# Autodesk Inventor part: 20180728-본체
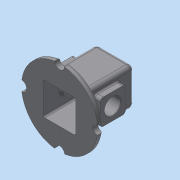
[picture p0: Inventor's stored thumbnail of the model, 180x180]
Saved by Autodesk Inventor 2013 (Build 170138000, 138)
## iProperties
Created: 2018-07
Part Number: 20180728-본체
Material: 일반
Document SubType Name: Modeling
Designer: dgall
Density: 1 g/cm^3
Author: dgall
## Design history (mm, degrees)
sketch "스케치1"
  geometry: A1 r 10 centre (0, -75) between (9.978, -74.333) and (-9.978, -74.333); A2 r 10 centre (-75, 0) between (-74.333, -9.978) and (-74.333, 9.978); A3 r 10 centre (0, 75) between (-9.978, 74.333) and (9.978, 74.333); A4 r 10 centre (75, 0) between (74.333, 9.978) and (74.333, -9.978); A5 r 75 centre (0, 0) between (-74.333, -9.978) and (-9.978, -74.333); A6 r 75 centre (0, 0) between (-9.978, 74.333) and (-74.333, 9.978); A7 r 75 centre (0, 0) between (9.978, -74.333) and (74.333, -9.978); A8 r 75 centre (0, 0) between (74.333, 9.978) and (9.978, 74.333); 1 further point
  constraints: 16 point on circle, 8 centre point, 6 equal radius, 2 horizontal alignment, 2 vertical alignment, 1 coincident
  dimensions: "d2" = 20 diameter of A1; "d3" = 75 radius of A7; "d4" = 75 distance of point (0, 0) A1.centre; "d5" = 150 distance of A2.centre A4.centre; "d6" = 75 distance of point (0, 0) A4.centre; "d7" = 75 distance of A3.centre point (0, 0)
extrude "돌출1" new body sketch "스케치1" distance "d8" = 10; taper "d9" = 0 deg
sketch "스케치2"
  geometry: L1 (-9.978, 0)-(-74.333, 0) reference; L2 (-9.978, 0)-(-9.978, -10) reference; L3 (-74.333, -10)-(-9.978, -10) reference; L4 (-74.333, 0)-(-74.333, -10) reference; L5 (9.978, 0)-(-9.978, 0) reference; L6 (9.978, 0)-(9.978, -10) reference; L7 (-9.978, -10)-(9.978, -10) reference; L8 (-9.978, 0)-(-9.978, -10) reference; L9 (74.333, 0)-(9.978, 0) reference; L10 (74.333, 0)-(74.333, -10) reference; L11 (9.978, -10)-(74.333, -10) reference; L12 (9.978, 0)-(9.978, -10) reference; L13 (-37, 0)-(-37, 100); L14 (-37, 100)-(37, 100); L15 (37, 100)-(37, 0); L16 (32, -10)-(32, 95); L17 (32, 95)-(-32, 95); L18 (-32, 95)-(-32, -10); L19 (-32, -10)-(32, -10); L20 (-37, 0)-(37, 0); 4 further points
  constraints: 16 end point, 4 midpoint, 4 perpendicular, 2 parallel, 2 point on line, 1 collinear, 1 vertical alignment
  dimensions: "d10" = 74 distance of L13.end L14.end; "d12" = 110 distance between parallel lines of L11 L14; "d13" = 5 distance between parallel lines of L14 L17; "d14" = 5 distance between parallel lines of L15 L16; "d15" = 5 distance between parallel lines of L13 L18
  node "투영된 루프1"
  node "투영된 루프2"
  node "투영된 루프3"
extrude "돌출2" join sketch "스케치2" stored distance "d16" = 74; taper "d17" = 0 deg
extrude "돌출3" cut sketch "스케치2" stored distance "d18" = 64; taper "d19" = 0 deg
sketch "스케치3"
  geometry: L1 (17, 57)-(57, 57); L2 (57, 57)-(57, 17); L3 (57, 17)-(17, 17); L4 (17, 17)-(17, 57); L5 (19.5, 54.5)-(54.5, 54.5); L6 (54.5, 54.5)-(54.5, 19.5); L7 (54.5, 19.5)-(19.5, 19.5); L8 (19.5, 19.5)-(19.5, 54.5); 5 further points
  constraints: 16 end point, 4 midpoint, 4 parallel, 4 perpendicular, 2 horizontal, 2 horizontal alignment, 2 vertical alignment
  dimensions: "d20" = 40 distance of L1.start L1.end; "d22" = 35 distance of L5.start L5.end
extrude "돌출4" join sketch "스케치3" distance "d23" = 7; taper "d24" = 0 deg
extrude "돌출5" join sketch "스케치3" distance "d25" = 10; taper "d26" = 0 deg
hole "구멍1" diameter "d29" = 21; stored, may be unused: countersink angle "d33" = 90 deg, drill point angle "d35" = 118 deg; dims "d27" = 17.5, "d28" = 17.5, "d30" = 6, "d31" = 28, "d32" = 4, "d34" = 8
sketch "스케치5"
  geometry: L1 (-74, 100)-(0, 100) reference; L2 (-62, 70)-(-12, 70); L3 (-12, 70)-(-12, 20); L4 (-12, 20)-(-62, 20); L5 (-62, 20)-(-62, 70); L6 (-62, 45)-(-12, 45); L7 (-27.022, -10)-(37.333, -10) reference; 3 further points
  constraints: 10 end point, 4 midpoint, 2 parallel, 2 perpendicular, 1 horizontal, 1 vertical alignment
  dimensions: "d37" = 50 distance of L2.start L2.end; "d39" = 55 distance between parallel lines of L7 L6
extrude "돌출6" join sketch "스케치5" distance "d40" = 13; taper "d41" = 0 deg
sketch "스케치6"
  geometry: L1 (0, 105)-(-64, 105) reference; L2 (-106.333, 0)-(-41.978, 0) reference; C1 r 25 at (-32, 55); 2 further points
  constraints: 1 centre point, 1 midpoint, 1 vertical alignment
  dimensions: "d42" = 55 distance from line of L2 C1.centre; "d43" = 50 diameter of C1
extrude "돌출7" join sketch "스케치6" distance "d44" = 7; taper "d45" = -20 deg
hole "구멍2" diameter "d48" = 32; stored, may be unused: countersink angle "d52" = 90 deg, drill point angle "d54" = 118 deg; dims "d46" = 25, "d47" = 25, "d49" = 6, "d50" = 4, "d51" = 2, "d53" = 8
fillet "모깎기1" dims "d55" = 6
hole "구멍3" diameter "d58" = 3.242; stored, may be unused: countersink angle "d62" = 90 deg, drill point angle "d64" = 118 deg; dims "d56" = 10, "d57" = 10, "d59" = 8, "d60" = 4, "d61" = 2, "d63" = 10
hole "구멍4" diameter "d67" = 3.242; stored, may be unused: countersink angle "d71" = 90 deg, drill point angle "d73" = 118 deg; dims "d65" = 10, "d66" = 10, "d68" = 8, "d69" = 4, "d70" = 2, "d72" = 10
hole "구멍5" diameter "d76" = 3.242; stored, may be unused: countersink angle "d80" = 90 deg, drill point angle "d82" = 118 deg; dims "d74" = 10, "d75" = 10, "d77" = 8, "d78" = 4, "d79" = 2, "d81" = 10
hole "구멍6" diameter "d85" = 3.242; stored, may be unused: countersink angle "d89" = 90 deg, drill point angle "d91" = 118 deg; dims "d83" = 10, "d84" = 10, "d86" = 8, "d87" = 4, "d88" = 2, "d90" = 10
hole "구멍7" diameter "d94" = 3.242; stored, may be unused: countersink angle "d98" = 90 deg, drill point angle "d100" = 118 deg; dims "d92" = 10, "d93" = 10, "d95" = 8, "d96" = 4, "d97" = 2, "d99" = 10
hole "구멍8" diameter "d103" = 3.242; stored, may be unused: countersink angle "d107" = 90 deg, drill point angle "d109" = 118 deg; dims "d101" = 10, "d102" = 10, "d104" = 8, "d105" = 4, "d106" = 2, "d108" = 10
hole "구멍9" diameter "d112" = 3.242; stored, may be unused: countersink angle "d116" = 90 deg, drill point angle "d118" = 118 deg; dims "d110" = 10, "d111" = 10, "d113" = 8, "d114" = 4, "d115" = 2, "d117" = 10
hole "구멍10" diameter "d121" = 3.242; stored, may be unused: countersink angle "d125" = 90 deg, drill point angle "d127" = 118 deg; dims "d119" = 10, "d120" = 10, "d122" = 8, "d123" = 4, "d124" = 2, "d126" = 10
fillet "모깎기2" dims "d128" = 3
fillet "모깎기3" dims "d129" = 3
fillet "모깎기4" dims "d130" = 8
fillet "모깎기5" dims "d131" = 8
fillet "모깎기6" dims "d132" = 3
fillet "모깎기7" dims "d133" = 3
fillet "모깎기8" dims "d134" = 3
fillet "모깎기9" dims "d135" = 3
chamfer "모따기1" distance "d136" = 1; stored, may be unused: second distance "d137" = 2, angle "d138" = 45 deg
node "솔리드1"
mirror "대칭1"
